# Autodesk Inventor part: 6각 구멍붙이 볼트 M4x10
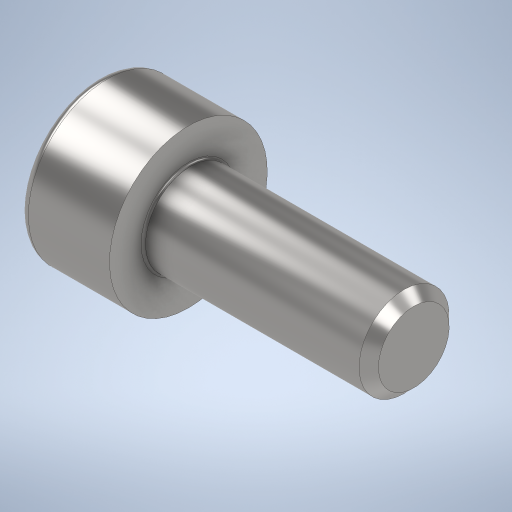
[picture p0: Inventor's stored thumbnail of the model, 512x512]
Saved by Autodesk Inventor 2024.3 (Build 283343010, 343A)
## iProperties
Created: 2025-11
Part Number: 6각 구멍붙이 볼트 M4x10
Material: 강철, 연강
Description: 6각머리 태핑 나사
Document SubType Name: Modeling
Designer: PC2-15
Density: 7.85 g/cm^3
Appearance: 기본값
Author: jhkim
Sending System: Autodesk Inventor 2026
Preprocessor: ST-DEVELOPER v20.1
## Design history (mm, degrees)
node "6각 구멍붙이 볼트 M4x101"
node "솔리드1"
body "Solid1"
